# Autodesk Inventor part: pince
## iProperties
Created: 2011-09
Part Number: pince
Document SubType Name: Modeling
Designer: Dominique
Author: Dominique
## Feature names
1. Extrusion1
2. Extrusion2
3. Perçage1 [Hole]
